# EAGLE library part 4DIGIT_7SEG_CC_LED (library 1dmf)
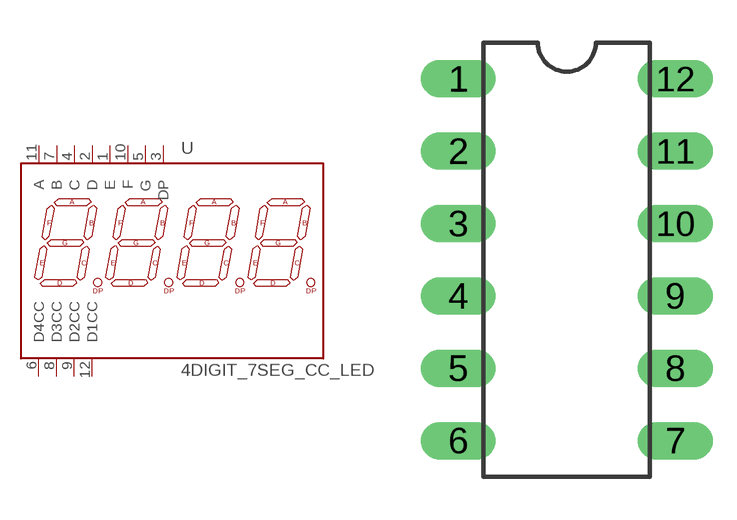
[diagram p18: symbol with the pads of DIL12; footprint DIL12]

Designator prefix -

## 4DIGIT_7SEG_CC_LED  [DIL12]
1  E  pas
2  D  pas
3  DP  pas
4  C  pas
5  G  pas
6  D4CC  pas
7  B  pas
8  D3CC  pas
9  D2CC  pas
10  F  pas
11  A  pas
12  D1CC  pas

## Footprint DIL12 (pad centres in mm)
drill 0.813 long: 1 -3.81,8.89; 2 -3.81,6.35; 3 -3.81,3.81; 4 -3.81,1.27; 5 -3.81,-1.27; 6 -3.81,-3.81; 7 3.81,-3.81; 8 3.81,-1.27; 9 3.81,1.27; 10 3.81,3.81; 11 3.81,6.35; 12 3.81,8.89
